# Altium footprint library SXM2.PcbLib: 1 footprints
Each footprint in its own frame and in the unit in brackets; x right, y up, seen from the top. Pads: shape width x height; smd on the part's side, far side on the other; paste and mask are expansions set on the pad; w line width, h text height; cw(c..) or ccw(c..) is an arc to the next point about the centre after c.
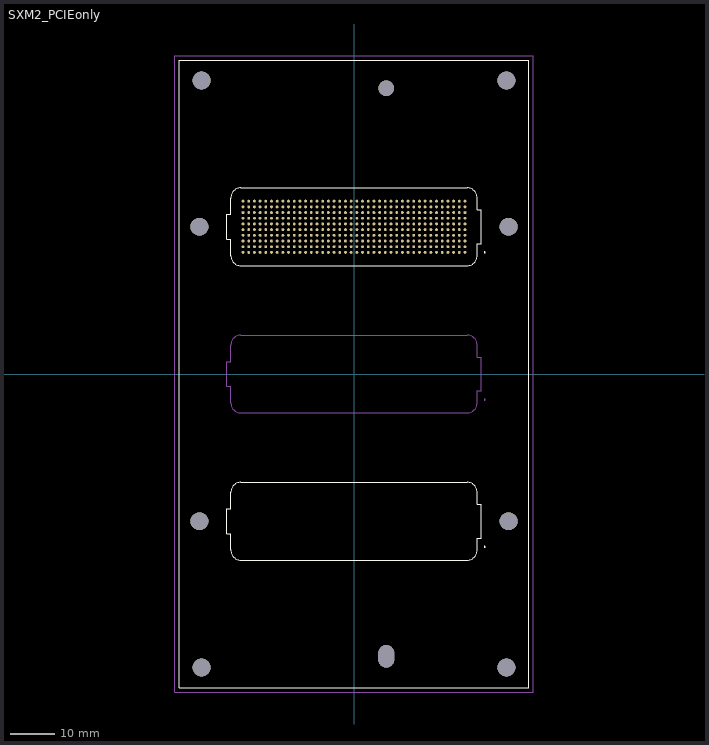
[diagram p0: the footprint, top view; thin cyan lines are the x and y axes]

## SXM2_PCIEonly [mm]
pads (410):
  round 0.64 smd paste+0 mask+0: A1(24.765,27.135) A2(23.495,27.135) A3(22.225,27.135) A4(20.955,27.135) A5(19.685,27.135) A6(18.415,27.135) A7(17.145,27.135) A8(15.875,27.135) A9(14.605,27.135) A10(13.335,27.135) A11(12.065,27.135) A12(10.795,27.135) A13(9.525,27.135) A14(8.255,27.135) A15(6.985,27.135) A16(5.715,27.135) A17(4.445,27.135) A18(3.175,27.135) A19(1.905,27.135) A20(0.635,27.135) A21(-0.635,27.135) A22(-1.905,27.135) A23(-3.175,27.135) A24(-4.445,27.135) A25(-5.715,27.135) A26(-6.985,27.135) A27(-8.255,27.135) A28(-9.525,27.135) A29(-10.795,27.135) A30(-12.065,27.135) A31(-13.335,27.135) A32(-14.605,27.135) A33(-15.875,27.135) A34(-17.145,27.135) A35(-18.415,27.135) A36(-19.685,27.135) A37(-20.955,27.135) A38(-22.225,27.135) A39(-23.495,27.135) A40(-24.765,27.135) B1(24.765,28.405) B2(23.495,28.405) B3(22.225,28.405) B4(20.955,28.405) B5(19.685,28.405) B6(18.415,28.405) B7(17.145,28.405) B8(15.875,28.405) B9(14.605,28.405) B10(13.335,28.405) B11(12.065,28.405) B12(10.795,28.405) B13(9.525,28.405) B14(8.255,28.405) B15(6.985,28.405) B16(5.715,28.405) B17(4.445,28.405) B18(3.175,28.405) B19(1.905,28.405) B20(0.635,28.405) B21(-0.635,28.405) B22(-1.905,28.405) B23(-3.175,28.405) B24(-4.445,28.405) B25(-5.715,28.405) B26(-6.985,28.405) B27(-8.255,28.405) B28(-9.525,28.405) B29(-10.795,28.405) B30(-12.065,28.405) B31(-13.335,28.405) B32(-14.605,28.405) B33(-15.875,28.405) B34(-17.145,28.405) B35(-18.415,28.405) B36(-19.685,28.405) B37(-20.955,28.405) B38(-22.225,28.405) B39(-23.495,28.405) B40(-24.765,28.405) C1(24.765,29.675) C2(23.495,29.675) C3(22.225,29.675) C4(20.955,29.675) C5(19.685,29.675) C6(18.415,29.675) C7(17.145,29.675) C8(15.875,29.675) C9(14.605,29.675) C10(13.335,29.675) C11(12.065,29.675) C12(10.795,29.675) C13(9.525,29.675) C14(8.255,29.675) C15(6.985,29.675) C16(5.715,29.675) C17(4.445,29.675) C18(3.175,29.675) C19(1.905,29.675) C20(0.635,29.675) C21(-0.635,29.675) C22(-1.905,29.675) C23(-3.175,29.675) C24(-4.445,29.675) C25(-5.715,29.675) C26(-6.985,29.675) C27(-8.255,29.675) C28(-9.525,29.675) C29(-10.795,29.675) C30(-12.065,29.675) C31(-13.335,29.675) C32(-14.605,29.675) C33(-15.875,29.675) C34(-17.145,29.675) C35(-18.415,29.675) C36(-19.685,29.675) C37(-20.955,29.675) C38(-22.225,29.675) C39(-23.495,29.675) C40(-24.765,29.675) D1(24.765,30.945) D2(23.495,30.945) D3(22.225,30.945) D4(20.955,30.945) D5(19.685,30.945) D6(18.415,30.945) D7(17.145,30.945) D8(15.875,30.945) D9(14.605,30.945) D10(13.335,30.945) D11(12.065,30.945) D12(10.795,30.945) D13(9.525,30.945) D14(8.255,30.945) D15(6.985,30.945) D16(5.715,30.945) D17(4.445,30.945) D18(3.175,30.945) D19(1.905,30.945) D20(0.635,30.945) D21(-0.635,30.945) D22(-1.905,30.945) D23(-3.175,30.945) D24(-4.445,30.945) D25(-5.715,30.945) D26(-6.985,30.945) D27(-8.255,30.945) D28(-9.525,30.945) D29(-10.795,30.945) D30(-12.065,30.945) D31(-13.335,30.945) D32(-14.605,30.945) D33(-15.875,30.945) D34(-17.145,30.945) D35(-18.415,30.945) D36(-19.685,30.945) D37(-20.955,30.945) D38(-22.225,30.945) D39(-23.495,30.945) D40(-24.765,30.945) E1(24.765,32.215) E2(23.495,32.215) E3(22.225,32.215) E4(20.955,32.215) E5(19.685,32.215) E6(18.415,32.215) E7(17.145,32.215) E8(15.875,32.215) E9(14.605,32.215) E10(13.335,32.215) E11(12.065,32.215) E12(10.795,32.215) E13(9.525,32.215) E14(8.255,32.215) E15(6.985,32.215) E16(5.715,32.215) E17(4.445,32.215) E18(3.175,32.215) E19(1.905,32.215) E20(0.635,32.215) E21(-0.635,32.215) E22(-1.905,32.215) E23(-3.175,32.215) E24(-4.445,32.215) E25(-5.715,32.215) E26(-6.985,32.215) E27(-8.255,32.215) E28(-9.525,32.215) E29(-10.795,32.215) E30(-12.065,32.215) E31(-13.335,32.215) E32(-14.605,32.215) E33(-15.875,32.215) E34(-17.145,32.215) E35(-18.415,32.215) E36(-19.685,32.215) E37(-20.955,32.215) E38(-22.225,32.215) E39(-23.495,32.215) E40(-24.765,32.215) F1(24.765,33.485) F2(23.495,33.485) F3(22.225,33.485) F4(20.955,33.485) F5(19.685,33.485) F6(18.415,33.485) F7(17.145,33.485) F8(15.875,33.485) F9(14.605,33.485) F10(13.335,33.485) F11(12.065,33.485) F12(10.795,33.485) F13(9.525,33.485) F14(8.255,33.485) F15(6.985,33.485) F16(5.715,33.485) F17(4.445,33.485) F18(3.175,33.485) F19(1.905,33.485) F20(0.635,33.485) F21(-0.635,33.485) F22(-1.905,33.485) F23(-3.175,33.485) F24(-4.445,33.485) F25(-5.715,33.485) F26(-6.985,33.485) F27(-8.255,33.485) F28(-9.525,33.485) F29(-10.795,33.485) F30(-12.065,33.485) F31(-13.335,33.485) F32(-14.605,33.485) F33(-15.875,33.485) F34(-17.145,33.485) F35(-18.415,33.485) F36(-19.685,33.485) F37(-20.955,33.485) F38(-22.225,33.485) F39(-23.495,33.485) F40(-24.765,33.485) G1(24.765,34.755) G2(23.495,34.755) G3(22.225,34.755) G4(20.955,34.755) G5(19.685,34.755) G6(18.415,34.755) G7(17.145,34.755) G8(15.875,34.755) G9(14.605,34.755) G10(13.335,34.755) G11(12.065,34.755) G12(10.795,34.755) G13(9.525,34.755) G14(8.255,34.755) G15(6.985,34.755) G16(5.715,34.755) G17(4.445,34.755) G18(3.175,34.755) G19(1.905,34.755) G20(0.635,34.755) G21(-0.635,34.755) G22(-1.905,34.755) G23(-3.175,34.755) G24(-4.445,34.755) G25(-5.715,34.755) G26(-6.985,34.755) G27(-8.255,34.755) G28(-9.525,34.755) G29(-10.795,34.755) G30(-12.065,34.755) G31(-13.335,34.755) G32(-14.605,34.755) G33(-15.875,34.755) G34(-17.145,34.755) G35(-18.415,34.755) G36(-19.685,34.755) G37(-20.955,34.755) G38(-22.225,34.755) G39(-23.495,34.755) G40(-24.765,34.755) H1(24.765,36.025) H2(23.495,36.025) H3(22.225,36.025) H4(20.955,36.025) H5(19.685,36.025) H6(18.415,36.025) H7(17.145,36.025) H8(15.875,36.025) H9(14.605,36.025) H10(13.335,36.025) H11(12.065,36.025) H12(10.795,36.025) H13(9.525,36.025) H14(8.255,36.025) H15(6.985,36.025) H16(5.715,36.025) H17(4.445,36.025) H18(3.175,36.025) H19(1.905,36.025) H20(0.635,36.025) H21(-0.635,36.025) H22(-1.905,36.025) H23(-3.175,36.025) H24(-4.445,36.025) H25(-5.715,36.025) H26(-6.985,36.025) H27(-8.255,36.025) H28(-9.525,36.025) H29(-10.795,36.025) H30(-12.065,36.025) H31(-13.335,36.025) H32(-14.605,36.025) H33(-15.875,36.025) H34(-17.145,36.025) H35(-18.415,36.025) H36(-19.685,36.025) H37(-20.955,36.025) H38(-22.225,36.025) H39(-23.495,36.025) H40(-24.765,36.025) J1(24.765,37.295) J2(23.495,37.295) J3(22.225,37.295) J4(20.955,37.295) J5(19.685,37.295) J6(18.415,37.295) J7(17.145,37.295) J8(15.875,37.295) J9(14.605,37.295) J10(13.335,37.295) J11(12.065,37.295) J12(10.795,37.295) J13(9.525,37.295) J14(8.255,37.295) J15(6.985,37.295) J16(5.715,37.295) J17(4.445,37.295) J18(3.175,37.295) J19(1.905,37.295) J20(0.635,37.295) J21(-0.635,37.295) J22(-1.905,37.295) J23(-3.175,37.295) J24(-4.445,37.295) J25(-5.715,37.295) J26(-6.985,37.295) J27(-8.255,37.295) J28(-9.525,37.295) J29(-10.795,37.295) J30(-12.065,37.295) J31(-13.335,37.295) J32(-14.605,37.295) J33(-15.875,37.295) J34(-17.145,37.295) J35(-18.415,37.295) J36(-19.685,37.295) J37(-20.955,37.295) J38(-22.225,37.295) J39(-23.495,37.295) J40(-24.765,37.295) K1(24.765,38.565) K2(23.495,38.565) K3(22.225,38.565) K4(20.955,38.565) K5(19.685,38.565) K6(18.415,38.565) K7(17.145,38.565) K8(15.875,38.565) K9(14.605,38.565) K10(13.335,38.565) K11(12.065,38.565) K12(10.795,38.565) K13(9.525,38.565) K14(8.255,38.565) K15(6.985,38.565) K16(5.715,38.565) K17(4.445,38.565) K18(3.175,38.565) K19(1.905,38.565) K20(0.635,38.565) K21(-0.635,38.565) K22(-1.905,38.565) K23(-3.175,38.565) K24(-4.445,38.565) K25(-5.715,38.565) K26(-6.985,38.565) K27(-8.255,38.565) K28(-9.525,38.565) K29(-10.795,38.565) K30(-12.065,38.565) K31(-13.335,38.565) K32(-14.605,38.565) K33(-15.875,38.565) K34(-17.145,38.565) K35(-18.415,38.565) K36(-19.685,38.565) K37(-20.955,38.565) K38(-22.225,38.565) K39(-23.495,38.565) K40(-24.765,38.565)
  round 4 hole 4 unplated paste-2539.97 mask+0: ""(-34.5,-32.85) ""(-34.5,32.85) ""(-34,-65.5) ""(-34,65.5) ""(34,-65.5) ""(34,65.5) ""(34.5,-32.85) ""(34.5,32.85)
  oval 3.5x5 hole 3.5 slot 5 at 90 deg unplated paste-2539.97 mask+0: ""(7.2,-63)
  round 3.5 hole 3.5 unplated paste-2539.97 mask+0: ""(7.2,63.75)
Top Overlay:
  circle w0.2: c29.15,27.135 r0.1
  circle w0.2: c29.15,-38.565 r0.1
  lines w0.1: -39,-70 -39,70 39,70 39,-70 -39,-70
  lines w0.127: 27.5,-39.35 27.5,-36.6 28.4,-36.6 28.4,-29.1 27.5,-29.1 27.5,-26.43 ccw(c25.25,-26.43) 25.25,-24.18 -25.25,-24.18 ccw(c-25.25,-26.43) -27.5,-26.43 -27.5,-30.1 -28.4,-30.1 -28.4,-35.6 -27.5,-35.6 -27.5,-39.27 ccw(c-25.25,-39.27) -25.25,-41.52 25.25,-41.52 ccw(c25.25,-39.27) 27.5,-39.27 ; 27.5,26.35 27.5,29.1 28.4,29.1 28.4,36.6 27.5,36.6 27.5,39.27 ccw(c25.25,39.27) 25.25,41.52 -25.25,41.52 ccw(c-25.25,39.27) -27.5,39.27 -27.5,35.6 -28.4,35.6 -28.4,30.1 -27.5,30.1 -27.5,26.43 ccw(c-25.25,26.43) -25.25,24.18 25.25,24.18 ccw(c25.25,26.43) 27.5,26.43
Mechanical 15:
  circle w0.2: c29.15,-5.715 r0.1
  lines w0.05: -40,-71 40,-71 40,71 -40,71 -40,-71
  lines w0.127: -28.4,-2.75 -28.4,2.75 -27.5,2.75 -27.5,6.42 cw(c-25.25,6.42) -25.25,8.67 25.25,8.67 cw(c25.25,6.42) 27.5,6.42 27.5,3.75 28.4,3.75 28.4,-3.75 27.5,-3.75 27.5,-6.42 cw(c25.25,-6.42) 25.25,-8.67 -25.25,-8.67 cw(c-25.25,-6.42) -27.5,-6.42 -27.5,-2.75 -28.4,-2.75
